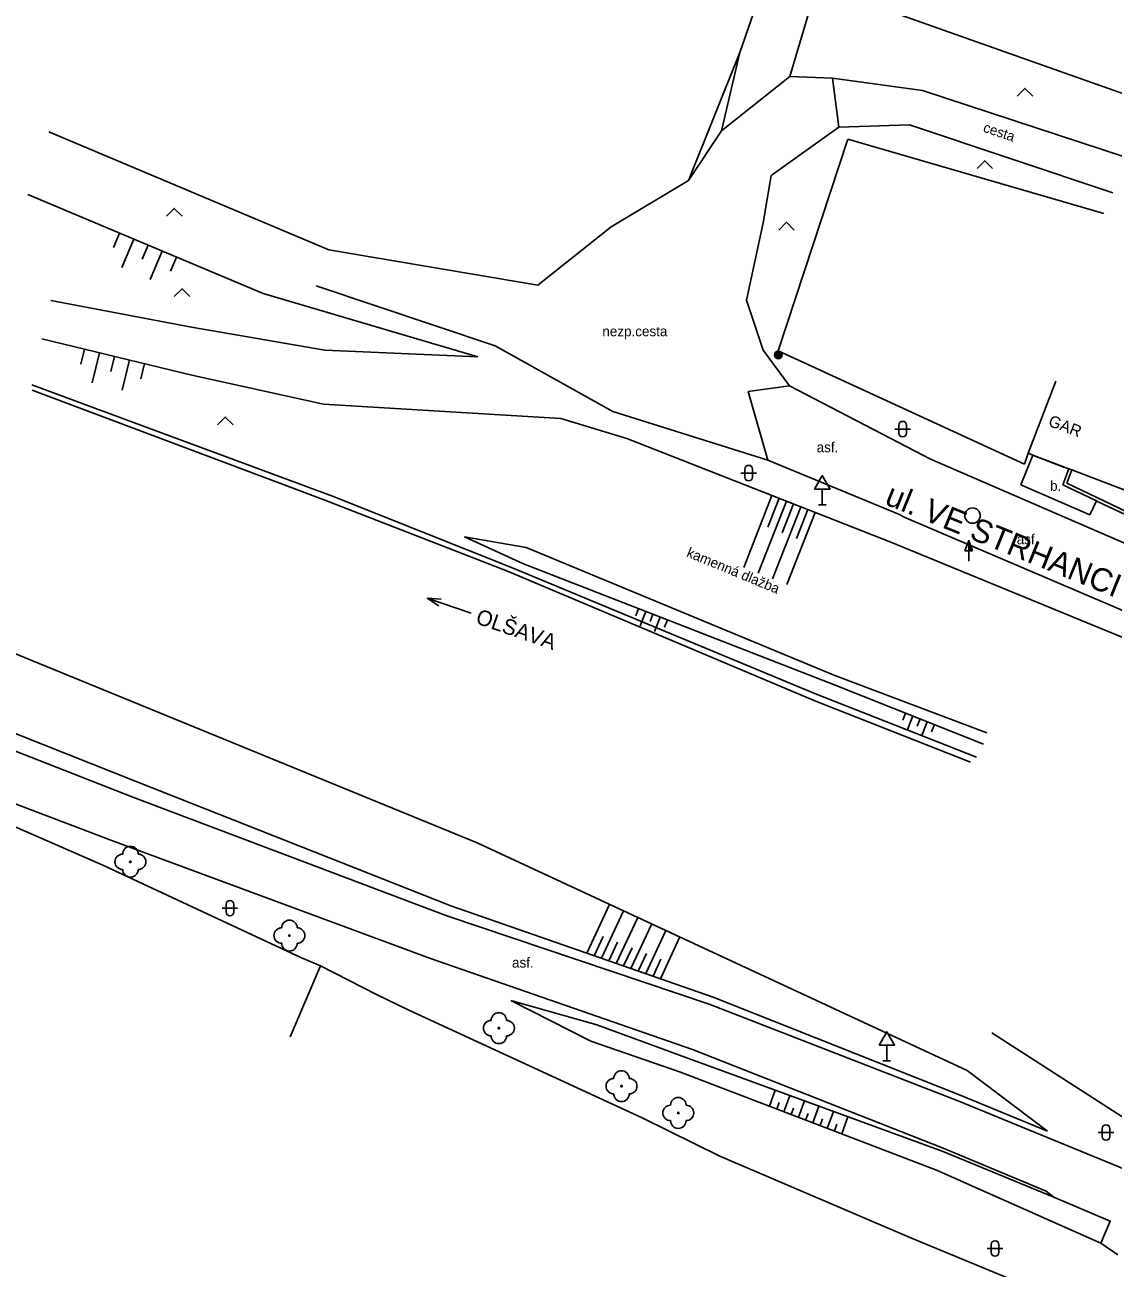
# Model space of a CAD drawing. Extents: x -539244 to -537359, y -1183785 to -1181851.
# Drawn here: x -538559.5 to -538489.1, y -1183313.6 to -1183233.2 of the extents above; entities that cross this region are included whole.
import ezdxf

# ---------------------------------------------------------------- set-up
doc = ezdxf.new("R2010")
doc.units = 0
for name, color, linetype in [('Vrstva 10', 7, 'Continuous'), ('Vrstva 11', 7, 'Continuous'), ('Vrstva 14', 7, 'Continuous'), ('Vrstva 15', 7, 'Continuous'), ('Vrstva 21', 7, 'Continuous'), ('Vrstva 22', 7, 'Continuous'), ('Vrstva 25', 7, 'Continuous'), ('Vrstva 27', 7, 'Continuous'), ('Vrstva 34', 7, 'Continuous'), ('Vrstva 36', 7, 'Continuous'), ('Vrstva 40', 7, 'Continuous'), ('Vrstva 41', 7, 'Continuous'), ('Vrstva 45', 7, 'Continuous'), ('Vrstva 49', 7, 'Continuous'), ('Vrstva 5', 7, 'Continuous'), ('Vrstva 6', 7, 'Continuous'), ('Vrstva 7', 7, 'Continuous'), ('Vrstva 8', 7, 'Continuous'), ('Vrstva 9', 7, 'Continuous')]:
    doc.layers.add(name, color=color, linetype=linetype)

msp = doc.modelspace()

# ---------------------------------------------------------------- linework, layer by layer
at = {"layer": 'Vrstva 10'}
for p, q in [((-538510.05, -1183256.52), (-538501.39, -1183261.03)), ((-538501.39, -1183261.03), (-538500.98, -1183261.26)), ((-538511.45, -1183261.34), (-538502.94, -1183264.85)), ((-538500.98, -1183261.26), (-538483.33, -1183268.9)), ((-538502.94, -1183264.85), (-538502.63, -1183265.03)), ((-538502.63, -1183265.03), (-538484.63, -1183272.71)), ((-538552.51, -1183283.13), (-538568.89, -1183276.7)), ((-538553.75, -1183285.98), (-538569.91, -1183279.82)), ((-538532.2, -1183290.81), (-538552.51, -1183283.13)), ((-538533.25, -1183293.57), (-538553.75, -1183285.98)), ((-538515.25, -1183296.51), (-538532.2, -1183290.81)), ((-538516.32, -1183299.45), (-538533.25, -1183293.57)), ((-538499.1, -1183302.78), (-538515.25, -1183296.51)), ((-538500.11, -1183305.83), (-538516.32, -1183299.45)), ((-538487.91, -1183307.39), (-538499.1, -1183302.78)), ((-538493.45, -1183308.61), (-538500.11, -1183305.83)), ((-538492.97, -1183309), (-538493.45, -1183308.61))]:
    msp.add_line(p, q, dxfattribs=at)
for points in [[(-538510.05, -1183256.52), (-538512.72, -1183256.89), (-538511.45, -1183261.34)], [(-538489.93, -1183311.98), (-538489.31, -1183310.56), (-538492.97, -1183309)]]:
    msp.add_lwpolyline(points, dxfattribs=at)
at = {"layer": 'Vrstva 11'}
for p, q in [((-538503.4, -1183206.19), (-538513.26, -1183234.98)), ((-538510.03, -1183236.52), (-538501.15, -1183206.59)), ((-538513.26, -1183234.98), (-538514.44, -1183240.03)), ((-538510.03, -1183236.52), (-538514.44, -1183240.03)), ((-538507.27, -1183236.64), (-538510.03, -1183236.52)), ((-538506.85, -1183239.8), (-538507.27, -1183236.64)), ((-538501.45, -1183237.42), (-538507.27, -1183236.64)), ((-538488.33, -1183241.75), (-538501.45, -1183237.42)), ((-538516.57, -1183243.25), (-538514.44, -1183240.03)), ((-538511.24, -1183242.93), (-538506.85, -1183239.8)), ((-538502.29, -1183239.65), (-538506.85, -1183239.8)), ((-538489.15, -1183244.04), (-538502.29, -1183239.65)), ((-538521.59, -1183246.24), (-538516.57, -1183243.25)), ((-538511.24, -1183242.93), (-538511.75, -1183245.98)), ((-538526.32, -1183250.01), (-538521.59, -1183246.24)), ((-538511.75, -1183245.98), (-538512.84, -1183250.99)), ((-538539.83, -1183247.74), (-538526.32, -1183250.01)), ((-538540.66, -1183250.06), (-538529.09, -1183253.95)), ((-538529.09, -1183253.95), (-538521.48, -1183258.18)), ((-538521.48, -1183258.18), (-538511.45, -1183261.34)), ((-538527.07, -1183266.99), (-538531.07, -1183266.3)), ((-538507.12, -1183275.26), (-538527.07, -1183266.99)), ((-538497.3, -1183278.97), (-538507.12, -1183275.26)), ((-538489.93, -1183311.98), (-538488.83, -1183312.72))]:
    msp.add_line(p, q, dxfattribs=at)
for points in [[(-538512.84, -1183250.99), (-538511.75, -1183254.22), (-538510.05, -1183256.52)], [(-538494.31, -1183261.005), (-538495.09, -1183262.93), (-538490.64, -1183264.87), (-538490.196, -1183263.972)]]:
    msp.add_lwpolyline(points, dxfattribs=at)
at = {"layer": 'Vrstva 14'}
for p, q in [((-538559.29, -1183244.16), (-538544.07, -1183250.56)), ((-538530.25, -1183286.08), (-538621.36, -1183248.75)), ((-538544.07, -1183250.56), (-538540.71, -1183251.55)), ((-538557.8, -1183251.02), (-538548.72, -1183252.74)), ((-538540.71, -1183251.55), (-538530.19, -1183254.65)), ((-538548.72, -1183252.74), (-538540.09, -1183254.23)), ((-538558.39, -1183253.48), (-538548.68, -1183255.84)), ((-538540.09, -1183254.23), (-538530.19, -1183254.65)), ((-538548.68, -1183255.84), (-538540.18, -1183257.72)), ((-538559.03, -1183256.47), (-538539.6, -1183263.66)), ((-538540.2, -1183263.89), (-538559.01, -1183256.81)), ((-538540.18, -1183257.72), (-538524.83, -1183258.65)), ((-538524.83, -1183258.65), (-538520.57, -1183259.93)), ((-538528.28, -1183268.52), (-538540.2, -1183263.89)), ((-538539.6, -1183263.66), (-538528.02, -1183268.27)), ((-538531.07, -1183266.3), (-538527.25, -1183268.04)), ((-538528.02, -1183268.27), (-538508.37, -1183276.44)), ((-538527.25, -1183268.04), (-538507.2, -1183275.84)), ((-538508.42, -1183276.89), (-538528.28, -1183268.52)), ((-538552.18, -1183282.16), (-538568.48, -1183275.71)), ((-538508.37, -1183276.44), (-538497.95, -1183280.54)), ((-538507.2, -1183275.84), (-538497.51, -1183279.7)), ((-538498.35, -1183280.86), (-538508.42, -1183276.89)), ((-538531.95, -1183290.15), (-538552.18, -1183282.16)), ((-538498.57, -1183300.81), (-538530.25, -1183286.08)), ((-538514.99, -1183296.06), (-538531.95, -1183290.15)), ((-538522.89, -1183298.9), (-538528.06, -1183296.29)), ((-538522.5, -1183297.85), (-538528.06, -1183296.29)), ((-538499.01, -1183302.41), (-538514.99, -1183296.06)), ((-538516.52, -1183300.05), (-538522.5, -1183297.85)), ((-538517.1, -1183300.92), (-538522.89, -1183298.9)), ((-538486.81, -1183304.91), (-538496.97, -1183298.37)), ((-538500.19, -1183306.03), (-538516.52, -1183300.05)), ((-538500.54, -1183307.25), (-538517.1, -1183300.92)), ((-538493.36, -1183304.74), (-538498.57, -1183300.81)), ((-538493.36, -1183304.74), (-538499.01, -1183302.41)), ((-538492.97, -1183309), (-538500.19, -1183306.03)), ((-538489.93, -1183311.98), (-538500.54, -1183307.25))]:
    msp.add_line(p, q, dxfattribs=at)
at = {"layer": 'Vrstva 15'}
for p, q in [((-538553.366, -1183246.651), (-538553.753, -1183247.573)), ((-538552.444, -1183247.038), (-538553.219, -1183248.882)), ((-538551.522, -1183247.426), (-538551.91, -1183248.348)), ((-538550.6, -1183247.814), (-538551.375, -1183249.657)), ((-538549.678, -1183248.201), (-538550.066, -1183249.123)), ((-538555.636, -1183254.15), (-538555.873, -1183255.121)), ((-538554.665, -1183254.386), (-538555.137, -1183256.329)), ((-538553.693, -1183254.622), (-538553.929, -1183255.594)), ((-538552.721, -1183254.858), (-538553.194, -1183256.802)), ((-538551.75, -1183255.094), (-538551.986, -1183256.066)), ((-538511.184, -1183263.62), (-538513.013, -1183268.273)), ((-538510.253, -1183263.985), (-538512.082, -1183268.639)), ((-538510.718, -1183263.803), (-538511.45, -1183265.664)), ((-538509.322, -1183264.351), (-538511.152, -1183269.005)), ((-538509.788, -1183264.168), (-538510.519, -1183266.03)), ((-538508.392, -1183264.717), (-538510.221, -1183269.371)), ((-538508.857, -1183264.534), (-538509.589, -1183266.396)), ((-538519.808, -1183270.935), (-538519.989, -1183271.401)), ((-538519.342, -1183271.117), (-538519.705, -1183272.049)), ((-538518.876, -1183271.298), (-538519.057, -1183271.764)), ((-538518.41, -1183271.479), (-538518.773, -1183272.411)), ((-538517.944, -1183271.661), (-538518.125, -1183272.127)), ((-538502.541, -1183277.696), (-538502.726, -1183278.16)), ((-538502.077, -1183277.881), (-538502.447, -1183278.81)), ((-538501.612, -1183278.066), (-538501.797, -1183278.531)), ((-538501.147, -1183278.251), (-538501.518, -1183279.18)), ((-538500.683, -1183278.436), (-538500.868, -1183278.901)), ((-538523.145, -1183293.218), (-538521.679, -1183290.065)), ((-538522.196, -1183293.549), (-538520.772, -1183290.487)), ((-538521.247, -1183293.88), (-538519.866, -1183290.908)), ((-538520.298, -1183294.21), (-538518.959, -1183291.33)), ((-538519.349, -1183294.541), (-538518.052, -1183291.752)), ((-538522.671, -1183293.384), (-538522.093, -1183292.14)), ((-538521.722, -1183293.714), (-538521.161, -1183292.508)), ((-538518.4, -1183294.872), (-538517.145, -1183292.173)), ((-538520.773, -1183294.045), (-538520.228, -1183292.875)), ((-538519.824, -1183294.376), (-538519.296, -1183293.242)), ((-538518.875, -1183294.706), (-538518.364, -1183293.609)), ((-538511.346, -1183303.12), (-538510.966, -1183302.084)), ((-538510.878, -1183303.298), (-538510.726, -1183302.881)), ((-538510.411, -1183303.477), (-538510.027, -1183302.428)), ((-538509.477, -1183303.834), (-538509.088, -1183302.772)), ((-538509.944, -1183303.655), (-538509.79, -1183303.233)), ((-538509.01, -1183304.012), (-538508.853, -1183303.585)), ((-538508.543, -1183304.191), (-538508.149, -1183303.115)), ((-538507.609, -1183304.548), (-538507.21, -1183303.459)), ((-538506.675, -1183304.905), (-538506.271, -1183303.803)), ((-538508.076, -1183304.369), (-538507.917, -1183303.937)), ((-538507.142, -1183304.727), (-538506.981, -1183304.288))]:
    msp.add_line(p, q, dxfattribs=at)
at = {"layer": 'Vrstva 21'}
for p, q in [((-538506.06, -1183231.39), (-538487.28, -1183238.06)), ((-538513.26, -1183234.98), (-538516.57, -1183243.25)), ((-538539.83, -1183247.74), (-538557.94, -1183240.1))]:
    msp.add_line(p, q, dxfattribs=at)
at = {"layer": 'Vrstva 22'}
for centre in [(-538552.66, -1183287.31), (-538542.38, -1183292.08), (-538528.84, -1183298.07), (-538520.91, -1183301.82), (-538517.24, -1183303.55)]:
    msp.add_circle(centre, 0.05, dxfattribs=at)
for centre, start, end in [((-538553.16, -1183287.31), 90, 270), ((-538552.66, -1183286.81), 0, 180), ((-538552.16, -1183287.31), 270, 90), ((-538552.66, -1183287.81), 180, 0), ((-538542.88, -1183292.08), 90, 270), ((-538542.38, -1183291.58), 0, 180), ((-538541.88, -1183292.08), 270, 90), ((-538542.38, -1183292.58), 180, 0), ((-538528.84, -1183297.57), 0, 180), ((-538529.34, -1183298.07), 90, 270), ((-538528.34, -1183298.07), 270, 90), ((-538528.84, -1183298.57), 180, 0), ((-538521.41, -1183301.82), 90, 270), ((-538520.91, -1183301.32), 0, 180), ((-538520.41, -1183301.82), 270, 90), ((-538520.91, -1183302.32), 180, 0), ((-538517.24, -1183303.05), 0, 180), ((-538517.74, -1183303.55), 90, 270), ((-538516.74, -1183303.55), 270, 90), ((-538517.24, -1183304.05), 180, 0)]:
    msp.add_arc(centre, 0.5, start, end, dxfattribs=at)
at = {"layer": 'Vrstva 25'}
for p, q in [((-538498.713, -1183267.208), (-538498.46, -1183266.534)), ((-538498.46, -1183267.208), (-538498.713, -1183267.208)), ((-538498.46, -1183267.86), (-538498.46, -1183267.21))]:
    msp.add_line(p, q, dxfattribs=at)
for points in [[(-538498.21, -1183267.21), (-538498.46, -1183267.21), (-538498.46, -1183266.534), (-538498.46, -1183266.534)], [(-538498.268, -1183267.17), (-538498.421, -1183267.17), (-538498.421, -1183266.758)], [(-538498.325, -1183267.131), (-538498.381, -1183267.131), (-538498.381, -1183266.981)]]:
    msp.add_lwpolyline(points, close=True, dxfattribs=at)
for radius in [0.25, 0.2, 0.15, 0.1, 0.05]:
    msp.add_circle((-538510.77, -1183254.53), radius, dxfattribs=at)
at = {"layer": 'Vrstva 27'}
msp.add_circle((-538498.22, -1183264.92), 0.5, dxfattribs=at)
at = {"layer": 'Vrstva 34'}
for p, q in [((-538507.93, -1183263.204), (-538507.93, -1183264.22)), ((-538508.18, -1183264.22), (-538507.68, -1183264.22)), ((-538503.76, -1183299.164), (-538503.76, -1183300.18)), ((-538504.01, -1183300.18), (-538503.51, -1183300.18))]:
    msp.add_line(p, q, dxfattribs=at)
for points in [[(-538508.43, -1183263.204), (-538507.43, -1183263.204), (-538507.93, -1183262.336)], [(-538504.26, -1183299.164), (-538503.26, -1183299.164), (-538503.76, -1183298.296)]]:
    msp.add_lwpolyline(points, close=True, dxfattribs=at)
at = {"layer": 'Vrstva 36'}
for p, q in [((-538503.231, -1183259.325), (-538502.231, -1183259.325)), ((-538502.982, -1183259.074), (-538502.982, -1183259.575)), ((-538502.481, -1183259.074), (-538502.481, -1183259.575)), ((-538512.941, -1183261.921), (-538512.941, -1183262.422)), ((-538512.44, -1183261.921), (-538512.44, -1183262.422)), ((-538513.19, -1183262.172), (-538512.19, -1183262.172)), ((-538546.479, -1183290.055), (-538546.479, -1183290.556)), ((-538545.978, -1183290.055), (-538545.978, -1183290.556)), ((-538546.728, -1183290.306), (-538545.728, -1183290.306)), ((-538489.84, -1183304.567), (-538489.84, -1183305.068)), ((-538489.339, -1183304.567), (-538489.339, -1183305.068)), ((-538490.089, -1183304.818), (-538489.089, -1183304.818)), ((-538497.261, -1183312.314), (-538496.261, -1183312.314)), ((-538497.012, -1183312.063), (-538497.012, -1183312.564)), ((-538496.511, -1183312.063), (-538496.511, -1183312.564))]:
    msp.add_line(p, q, dxfattribs=at)
for points in [[(-538495.326, -1183237.792), (-538494.826, -1183237.292), (-538494.326, -1183237.792)], [(-538497.92, -1183242.471), (-538497.42, -1183241.971), (-538496.92, -1183242.471)], [(-538550.325, -1183245.554), (-538549.825, -1183245.054), (-538549.325, -1183245.554)], [(-538510.746, -1183246.454), (-538510.246, -1183245.954), (-538509.746, -1183246.454)], [(-538549.825, -1183250.752), (-538549.325, -1183250.252), (-538548.825, -1183250.752)], [(-538547.027, -1183259.049), (-538546.527, -1183258.549), (-538546.027, -1183259.049)]]:
    msp.add_lwpolyline(points, dxfattribs=at)
for centre, start, end in [((-538502.731, -1183259.075), 0, 180), ((-538502.731, -1183259.575), 180, 0), ((-538512.69, -1183261.922), 0, 180), ((-538512.69, -1183262.422), 180, 0), ((-538546.228, -1183290.056), 0, 180), ((-538546.228, -1183290.556), 180, 0), ((-538489.589, -1183304.568), 0, 180), ((-538489.589, -1183305.068), 180, 0), ((-538496.761, -1183312.064), 0, 180), ((-538496.761, -1183312.564), 180, 0)]:
    msp.add_arc(centre, 0.25, start, end, dxfattribs=at)
at = {"layer": 'Vrstva 45'}
msp.add_line((-538530.633, -1183271.236), (-538533.468, -1183270.256), dxfattribs=at)
msp.add_lwpolyline([(-538532.715, -1183270.76), (-538533.468, -1183270.256), (-538532.565, -1183270.325)], dxfattribs=at)
at = {"layer": 'Vrstva 5'}
for p, q in [((-538492.825, -1183256.219), (-538494.61, -1183260.89)), ((-538491.797, -1183261.964), (-538491.984, -1183261.893)), ((-538481.988, -1183265.713), (-538491.797, -1183261.964))]:
    msp.add_line(p, q, dxfattribs=at)
msp.add_lwpolyline([(-538491.984, -1183261.893), (-538494.31, -1183261.005), (-538494.61, -1183260.89)], dxfattribs=at)
at = {"layer": 'Vrstva 6'}
msp.add_line((-538494.27, -1183261.04), (-538492.27, -1183261.8), dxfattribs=at)
at = {"layer": 'Vrstva 7'}
for p, q in [((-538510.78, -1183254.26), (-538506.28, -1183240.57)), ((-538506.28, -1183240.57), (-538489.72, -1183245.39)), ((-538494.85, -1183261.59), (-538510.78, -1183254.26)), ((-538494.85, -1183261.59), (-538494.61, -1183260.89)), ((-538491.984, -1183261.893), (-538492.38, -1183262.93)), ((-538491.797, -1183261.964), (-538492.127, -1183262.829)), ((-538482.619, -1183267.366), (-538492.127, -1183262.829)), ((-538490.09, -1183264.023), (-538482.51, -1183267.64)), ((-538564.3, -1183283.23), (-538554.45, -1183287.52)), ((-538554.45, -1183287.52), (-538541.61, -1183293.52)), ((-538542.335, -1183298.619), (-538540.38, -1183294.03)), ((-538536.75, -1183295.9), (-538534.71, -1183296.89)), ((-538534.71, -1183296.89), (-538519.54, -1183303.88)), ((-538519.54, -1183303.88), (-538514.56, -1183306.35)), ((-538514.56, -1183306.35), (-538502.16, -1183311.64)), ((-538502.16, -1183311.64), (-538492.08, -1183315.81))]:
    msp.add_line(p, q, dxfattribs=at)
msp.add_lwpolyline([(-538492.38, -1183262.93), (-538490.196, -1183263.972), (-538490.09, -1183264.023)], dxfattribs=at)
at = {"layer": 'Vrstva 8'}
for p, q in [((-538540.38, -1183294.03), (-538541.61, -1183293.52)), ((-538536.75, -1183295.9), (-538540.38, -1183294.03))]:
    msp.add_line(p, q, dxfattribs=at)
at = {"layer": 'Vrstva 9'}
for p, q in [((-538503.5, -1183266.64), (-538520.57, -1183259.93)), ((-538485.3, -1183274.12), (-538503.5, -1183266.64))]:
    msp.add_line(p, q, dxfattribs=at)

# ---------------------------------------------------------------- texts
at = {"layer": 'Vrstva 40'}
for s, rotation, p in [('cesta', 341.52582, (-538497.579, -1183240.084)), ('kamenná dlažba', 337.48421, (-538516.753, -1183267.548))]:
    msp.add_text(s, height=0.65, rotation=rotation, dxfattribs=at).set_placement(p)
for s, p in [('nezp.cesta', (-538522.148, -1183253.325)), ('asf.', (-538508.296, -1183260.823)), ('b.', (-538493.202, -1183263.321)), ('asf.', (-538495.358, -1183266.773)), ('asf.', (-538527.99, -1183294.151))]:
    msp.add_text(s, height=0.65, dxfattribs=at).set_placement(p)
at = {"layer": 'Vrstva 41'}
msp.add_text('GAR', height=0.75, rotation=339.08977, dxfattribs=at).set_placement((-538493.374, -1183259.095))
at = {"layer": 'Vrstva 45'}
msp.add_text('OLŠAVA', height=1, rotation=340.93081, dxfattribs=at).set_placement((-538530.404, -1183271.869))
at = {"layer": 'Vrstva 49'}
msp.add_text('ul. VE STRHANCI', height=1.5, rotation=337.92395, dxfattribs=at).set_placement((-538503.969, -1183264.159))

doc.saveas('drawing.dxf')
